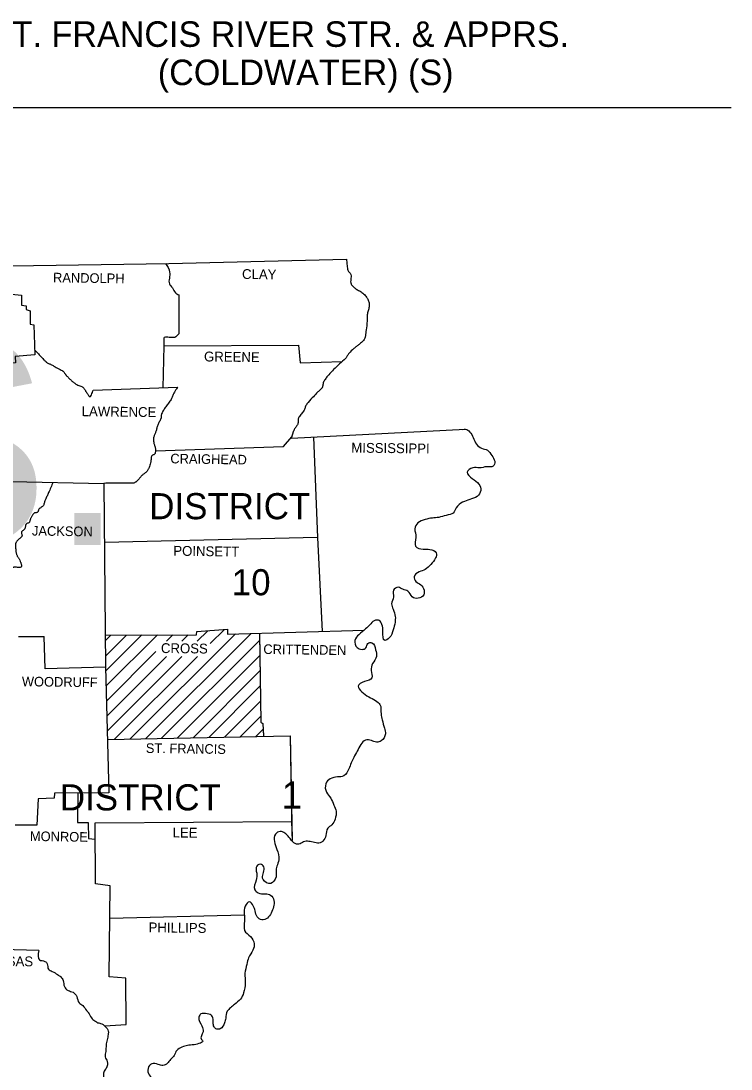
# Model space of a CAD drawing. Extents: x 1720274 to 1751788, y 372074 to 391887.
# Drawn here: x 1748526 to 1751788, y 386795 to 391611 of the extents above; entities that cross this region are included whole.
import ezdxf

# ---------------------------------------------------------------- set-up
doc = ezdxf.new("R2010")
doc.units = 0
for name, color, linetype in [('1', 7, 'Continuous'), ('Default', 7, 'Continuous'), ('G-Table-Major', 7, 'Continuous'), ('R_Draft', 7, 'Continuous')]:
    doc.layers.add(name, color=color, linetype=linetype)

msp = doc.modelspace()

# ---------------------------------------------------------------- linework, layer by layer
at = {"layer": '1'}
for p, q in [((1749768.5, 389693.6), (1749779.8, 389728.6)), ((1748513.7, 388782), (1748631.4, 388782))]:
    msp.add_line(p, q, dxfattribs=at)
for points in [[(1744246.4, 390467.3), (1745948.5, 390466.3), (1747442.1, 390469.4), (1749204.3, 390496.8), (1750021.1, 390515.7)], [(1748410.3, 390484.5), (1748406.4, 390452.6), (1748427.4, 390449.4), (1748426.4, 390436.8), (1748450.6, 390431.5), (1748452.7, 390414.7), (1748464.3, 390407.3), (1748467.4, 390356.8), (1748527.4, 390350.5), (1748527.4, 390305.2), (1748549.5, 390302), (1748549.5, 390284.2), (1748568.5, 390278.9), (1748567.4, 390217.8), (1748584.2, 390214.7), (1748588.5, 390076.8), (1748499, 390068.4), (1748500, 390038.9), (1748472.7, 390037.8), (1748482.1, 389494.7), (1748906.4, 389485.2), (1748913.7, 388641), (1748636.9, 388633.6), (1748631.4, 388782)], [(1749768.5, 389693.6), (1750567.4, 389734.7)], [(1748912.4, 388788.3), (1749332.7, 388790.4), (1749333.7, 388805.2), (1749474.8, 388815.7), (1749474.8, 388793.6), (1750101.8, 388810.8)], [(1748607.4, 387338.8), (1748209.5, 387349.3), (1748207.4, 387219.9), (1747402.2, 387216.7)]]:
    msp.add_lwpolyline(points, dxfattribs=at)
for points in [[(1750021.1, 390515.7), (1750022, 390504.1), (1750023.2, 390492.5), (1750024.7, 390481), (1750026.4, 390469.4), (1750028.8, 390462.9), (1750033.1, 390457), (1750037.7, 390451.3), (1750041.1, 390445.2), (1750042.4, 390434.5), (1750041.1, 390423), (1750040.3, 390411.5), (1750041.1, 390406.1), (1750043.2, 390401), (1750051.2, 390390.6), (1750061.1, 390382), (1750068.6, 390377), (1750076.4, 390372.6), (1750084.2, 390368.2), (1750091.6, 390363.1), (1750106.8, 390349.6), (1750113.3, 390341.8), (1750116.3, 390337.4), (1750119, 390332.6), (1750122.8, 390323.7), (1750125, 390314.7), (1750125.8, 390305.7), (1750125.3, 390296.8), (1750123.5, 390287.6), (1750120.9, 390278.4), (1750118.4, 390269.2), (1750116.9, 390259.9), (1750116.3, 390249.7), (1750115.9, 390239.4), (1750115.5, 390229.1), (1750114.8, 390218.9), (1750110.6, 390183.1), (1750108.6, 390166.6), (1750107, 390158.5), (1750105.8, 390154.5), (1750104.2, 390150.5), (1750093.3, 390135.9), (1750079, 390124.1), (1750072.9, 390119.4), (1750066.8, 390114.7), (1750060.7, 390110.1), (1750054.8, 390105.2), (1750032.7, 390083.1), (1750028.5, 390077.4), (1750025, 390071.3), (1750021.3, 390065.3), (1750016.9, 390059.9), (1749989.5, 390034.7), (1749962.1, 390008.4), (1749940, 389985.2), (1749934, 389978.2), (1749928.4, 389970.9), (1749923, 389963.4), (1749917.9, 389955.7), (1749914.7, 389947.8), (1749913.1, 389939.1), (1749911.3, 389930.5), (1749909.8, 389926.6), (1749907.4, 389923.1), (1749901.6, 389917.1), (1749895.3, 389911.4), (1749889.1, 389905.9), (1749883.2, 389899.9), (1749864.2, 389878.9), (1749839, 389850.5), (1749834.8, 389844), (1749832, 389836.7), (1749829.5, 389829.1), (1749826.4, 389822), (1749820.7, 389813.7), (1749814.1, 389805.8), (1749807.6, 389797.9), (1749802.1, 389789.4), (1749799.9, 389781.8), (1749799.3, 389773.7), (1749798.8, 389765.5), (1749796.9, 389757.8), (1749793.5, 389751.3), (1749789.3, 389745.1), (1749785, 389738.9), (1749781.1, 389732.6), (1749779.8, 389728.6)], [(1750555.8, 389733.6), (1750567.4, 389734.7), (1750603.2, 389696.8), (1750619, 389665.2), (1750642.1, 389647.3), (1750668.5, 389637.8), (1750688.5, 389613.6), (1750702.1, 389587.3), (1750694.8, 389564.1), (1750665.3, 389562), (1750632.7, 389556.8), (1750601.1, 389557.8), (1750575.8, 389536.8), (1750599, 389508.3), (1750629.5, 389482), (1750637.9, 389453.6), (1750621.1, 389426.2), (1750587.4, 389411.5), (1750554.8, 389398.9), (1750525.3, 389373.6), (1750511.6, 389349.4), (1750479, 389338.9), (1750445.3, 389329.4), (1750415.8, 389326.2), (1750382.1, 389319.9), (1750349.5, 389304.1), (1750335.8, 389276.8), (1750340, 389237.8), (1750339, 389196.8), (1750373.7, 389183.1), (1750404.2, 389182), (1750433.7, 389166.2), (1750430.6, 389143.1), (1750408.5, 389113.6), (1750382.1, 389090.4), (1750355.8, 389078.9), (1750331.6, 389056.8), (1750340, 389034.6), (1750362.1, 389019.9), (1750377.9, 388995.7), (1750375.8, 388973.6), (1750350.6, 388957.8), (1750323.2, 388964.1), (1750303.2, 388990.4), (1750280, 388998.9), (1750260, 389008.3), (1750236.9, 388994.6), (1750236.9, 388964.1), (1750228.5, 388931.5), (1750235.8, 388907.3), (1750245.3, 388873.6), (1750244.2, 388848.3), (1750235.8, 388812.5), (1750217.9, 388775.7), (1750196.9, 388764.1), (1750188.5, 388804.1), (1750184.3, 388836.7), (1750171.6, 388855.7), (1750154.8, 388856.7), (1750132.7, 388841), (1750108.5, 388816.7), (1750077.9, 388790.4), (1750060, 388764.1), (1750069.5, 388731.5), (1750092.7, 388723.1), (1750110.6, 388729.4), (1750120, 388750.4), (1750137.9, 388753.6), (1750154.8, 388721)], [(1750154.8, 388721), (1750159, 388690.4), (1750141.1, 388657.8), (1750134.8, 388625.2), (1750137.9, 388592.5), (1750104.2, 388574.6), (1750074.8, 388553.6), (1750091.6, 388528.3), (1750123.2, 388505.2), (1750154.8, 388487.3), (1750174.8, 388469.4), (1750180, 388426.2), (1750185.3, 388398.8), (1750195.8, 388360.9), (1750200, 388334.6), (1750181.1, 388303.1), (1750159, 388296.7), (1750135.8, 388304.1), (1750108.5, 388306.2), (1750086.4, 388285.2), (1750070.6, 388255.7), (1750054.8, 388226.2), (1750043.2, 388200.9), (1750031.6, 388173.6), (1750008.5, 388142), (1749980, 388136.7), (1749946.4, 388128.3), (1749926.4, 388105.2), (1749929.5, 388066.2), (1749948.5, 388039.9), (1749963.2, 388007.3), (1749973.7, 387978.8), (1749968.5, 387943), (1749953.7, 387916.7), (1749934.8, 387900.9), (1749926.4, 387867.3), (1749912.7, 387842), (1749900, 387833.6), (1749874.8, 387835.7), (1749847.4, 387840.9), (1749824.2, 387838.8), (1749802.1, 387827.2), (1749780, 387834.6), (1749756.9, 387859.9), (1749737.9, 387878.8), (1749716.9, 387886.2), (1749694.8, 387874.6), (1749690.6, 387839.9), (1749701.1, 387804.1), (1749710.6, 387755.7), (1749701.1, 387726.2), (1749697.9, 387677.8)], [(1749697.9, 387677.8), (1749673.7, 387647.2), (1749637.9, 387666.2), (1749637.9, 387691.5), (1749643.2, 387717.8), (1749630.6, 387734.6), (1749608.5, 387727.2), (1749608.5, 387694.6), (1749606.4, 387663), (1749600, 387617.8), (1749614.8, 387604.1), (1749648.5, 387599.9), (1749672.7, 387593.6), (1749687.4, 387569.3), (1749686.4, 387539.9), (1749674.8, 387511.5), (1749657.9, 387488.3), (1749631.6, 387479.9), (1749610.6, 387493.6), (1749602.1, 387520.9), (1749592.7, 387545.1), (1749574.8, 387563), (1749555.8, 387543), (1749551.6, 387506.2), (1749552.7, 387474.6), (1749552.7, 387431.5), (1749580, 387403), (1749596.9, 387370.4), (1749591.6, 387340.9), (1749571.6, 387306.2), (1749563.2, 387275.7), (1749554.8, 387234.6), (1749555.8, 387189.3), (1749548.5, 387145.1), (1749533.7, 387115.7), (1749506.4, 387091.4), (1749488.5, 387075.7), (1749473.7, 387059.9), (1749466.4, 387028.3), (1749461.1, 387006.2), (1749441.1, 386979.9), (1749425.3, 386977.8), (1749412.7, 386988.3), (1749408.5, 387006.2), (1749408.5, 387024.1), (1749400, 387042), (1749373.7, 387049.3), (1749352.7, 387048.3), (1749343.2, 387033.5), (1749356.9, 386992.5), (1749362.1, 386966.2), (1749354.8, 386930.4), (1749359, 386926.2), (1749321.1, 386906.2), (1749290.6, 386903), (1749265.3, 386895.6), (1749241.1, 386879.9), (1749229.5, 386856.7), (1749212.7, 386837.8), (1749197.9, 386819.9), (1749177.9, 386811.4), (1749155.8, 386815.6), (1749126.4, 386818.8), (1749109.5, 386797.8), (1749114.8, 386767.2), (1749134.8, 386749.3), (1749164.2, 386740.9), (1749194.8, 386743), (1749224.3, 386746.2), (1749251.6, 386731.4), (1749246.4, 386703), (1749220, 386689.3), (1749181.1, 386685.1), (1749149.5, 386688.3), (1749111.6, 386679.9), (1749092.7, 386655.6), (1749103.2, 386618.8), (1749144.3, 386604.1), (1749163.2, 386569.3), (1749164.2, 386536.7), (1749150.6, 386493.5), (1749131.6, 386473.5), (1749094.8, 386465.1), (1749066.4, 386459.8), (1749062.1, 386411.4), (1749049.5, 386387.2), (1749027.4, 386379.8), (1748995.8, 386395.6), (1748976.9, 386403), (1748953.7, 386413.5), (1748924.3, 386431.4), (1748902.1, 386428.3), (1748908.5, 386382), (1748910.6, 386379.8), (1748935.8, 386345.1), (1748961.1, 386317.7), (1748972.7, 386285.1)], [(1748607.4, 387338.8), (1748610.6, 387295.7), (1748635.8, 387289.3), (1748646.4, 387277.8), (1748651.6, 387253.6), (1748669.5, 387243), (1748693.7, 387228.3), (1748708.5, 387217.8), (1748719, 387200.9), (1748725.3, 387173.5), (1748742.1, 387155.7), (1748765.3, 387147.2), (1748782.1, 387127.2), (1748792.7, 387098.8), (1748809.5, 387086.2), (1748826.4, 387064.1), (1748834.8, 387054.6), (1748849.5, 387029.3), (1748864.3, 387016.7), (1748874.8, 387009.3), (1748891.6, 387004.1), (1748912.7, 386990.4), (1748926.4, 386969.3), (1748926.4, 386953.5), (1748921.1, 386929.3), (1748916.9, 386904.1), (1748914.8, 386875.6), (1748912.7, 386850.4), (1748922.1, 386829.3), (1748916.9, 386797.8), (1748906.4, 386780.9), (1748905.3, 386757.7), (1748902.1, 386723), (1748897.9, 386703), (1748888.5, 386670.4), (1748874.8, 386653.5)]]:
    msp.add_spline(points, degree=3, dxfattribs=at)
at = {"layer": 'Default'}
msp.add_line((1749183.3, 390117.8), (1749184.2, 390156.8), dxfattribs=at)
for points in [[(1749250.6, 390351.5), (1749250.6, 390173.6)], [(1749178.7, 389924.9), (1749183.3, 390117.8), (1749184.2, 390117.8), (1749800, 390121), (1749808.5, 390038.9), (1750001.7, 390045.9)], [(1748856.9, 389913.6), (1749245, 389927.2)], [(1749143.8, 389635.6), (1749731.6, 389654.7), (1749770.3, 389699.2)], [(1749869.3, 389698.8), (1749887.4, 389236.8), (1749908.8, 388805.5)], [(1749044.3, 389487.3), (1748915.8, 389487.3), (1748906.4, 389485.2)], [(1749887.4, 389236.8), (1748908.7, 389214.4)], [(1749622.1, 388797.6), (1749627.4, 388388.3), (1749636.9, 388382), (1749640.2, 388323.8)], [(1749622.1, 388793.6), (1749627.4, 388388.3), (1749636.9, 388382), (1749640, 388327.3)], [(1749622.1, 388793.6), (1749627.4, 388388.3), (1749636.9, 388382), (1749640, 388327.3)], [(1749622.1, 388793.6), (1749627.4, 388388.3), (1749636.9, 388382), (1749640, 388327.3)], [(1749622.1, 388793.6), (1749627.4, 388388.3), (1749636.9, 388382), (1749640, 388327.3)], [(1748913.7, 388641), (1748929.5, 388064.1), (1748679, 388063), (1748677.9, 388039.9), (1748605.3, 388035.7), (1748599, 387915.7), (1748499.2, 387915.7)], [(1748922.8, 388309.3), (1749762.1, 388326.2)], [(1749762.1, 388326.2), (1749770.6, 387865.1)], [(1749762.1, 388326.2), (1749770.6, 387865.1)], [(1749762.1, 388326.2), (1749770.6, 387865.1)], [(1749762.1, 388326.2), (1749770.6, 387865.1)], [(1749762.1, 388326.2), (1749770.6, 387865.1)], [(1749762.1, 388326.2), (1749770.6, 387865.1)], [(1749762.1, 388326.2), (1749770.6, 387865.1)], [(1749762.1, 388326.2), (1749771, 387844)], [(1748786.4, 388063.5), (1748785.3, 387927.3), (1748833.7, 387927.3), (1748835.8, 387854.6), (1748866.9, 387851.4)], [(1748910.3, 386992.5), (1749008.5, 386998.8), (1749007.4, 387212.5), (1748930.6, 387217.8), (1748934.8, 387635.7), (1748868.5, 387645.1), (1748866.4, 387926.2), (1749769.3, 387932.6)], [(1748933.3, 387487.2), (1749551.8, 387502.5)]]:
    msp.add_lwpolyline(points, dxfattribs=at)
for points in [[(1749189.4, 390496.6), (1749208.5, 390456.8), (1749207.4, 390428.4), (1749207.4, 390402.1), (1749221.1, 390384.2), (1749234.8, 390362), (1749250.6, 390351.5)], [(1749250.6, 390173.6), (1749232.7, 390156.8), (1749206.4, 390156.8), (1749184.2, 390156.8)], [(1748587.8, 390098.9), (1748605.4, 390080.4), (1748623.2, 390062), (1748625.7, 390059.5), (1748633, 390051.8), (1748637.9, 390046.8), (1748640.5, 390044.4), (1748641.8, 390043.2), (1748643.2, 390042), (1748648.6, 390038.5), (1748654.5, 390035.8), (1748660.5, 390033.3), (1748666.4, 390030.5), (1748680, 390022.6), (1748693.7, 390014.7), (1748699.8, 390011.5), (1748705.9, 390008.6), (1748715, 390003.9), (1748716.5, 390003), (1748717.9, 390002), (1748722.6, 389997.7), (1748726.3, 389992.5), (1748729.8, 389987.1), (1748731.7, 389984.5), (1748733.7, 389982), (1748744.6, 389970.8), (1748755.8, 389959.9), (1748761.2, 389955.2), (1748766.7, 389950.7), (1748772.3, 389946.3), (1748777.9, 389942), (1748786.6, 389937.6), (1748796.1, 389934.6), (1748805.3, 389931), (1748809.3, 389928.5), (1748811.1, 389927), (1748812.7, 389925.2), (1748815.8, 389920.9), (1748818.6, 389916.4), (1748821.3, 389911.8), (1748824.3, 389907.3), (1748826.2, 389904.4), (1748828.2, 389901.3), (1748832.1, 389895.2), (1748836.1, 389889.6), (1748838.1, 389887.2), (1748839.1, 389886.1), (1748839.6, 389885.6), (1748840, 389885.2), (1748841.2, 389884.5), (1748842.4, 389884.3), (1748844.8, 389885.7), (1748849.3, 389893.2), (1748853.5, 389903.8), (1748855.3, 389909.1), (1748856.9, 389913.6)], [(1749245, 389927.2), (1749236.1, 389914.4), (1749228.5, 389901), (1749225.2, 389893.7), (1749222.4, 389886.1), (1749219.4, 389878.6), (1749215.8, 389871.5), (1749209.9, 389862.8), (1749203.4, 389854.5), (1749196.8, 389846.3), (1749190.6, 389837.8), (1749180.4, 389821.9), (1749175.8, 389813.7), (1749171.6, 389805.2), (1749170.2, 389799.8), (1749169.9, 389794.2), (1749169.6, 389788.5), (1749168.5, 389783.1), (1749165, 389775.6), (1749160.9, 389768.4), (1749156.9, 389761.2), (1749153.7, 389753.6), (1749151.5, 389746.3), (1749149.5, 389738.9), (1749147.5, 389731.5), (1749145.3, 389724.1), (1749143, 389717.8), (1749140.5, 389711.6), (1749138, 389705.3), (1749135.8, 389698.9), (1749134.7, 389692.4), (1749134.5, 389685.8), (1749135, 389679.1), (1749135.8, 389672.6), (1749137.3, 389665.9), (1749139.4, 389659.4), (1749141.6, 389652.8), (1749143.2, 389646.2), (1749143.8, 389640.3), (1749143.7, 389634.1), (1749142.8, 389628), (1749142, 389625), (1749141.1, 389622), (1749137.9, 389618.4), (1749133, 389616.2), (1749128.2, 389614), (1749125.3, 389610.5), (1749124.5, 389606.7), (1749123.9, 389602.9), (1749123.2, 389595.2), (1749122.4, 389587.5), (1749121.1, 389579.9), (1749118.3, 389569.3), (1749114.8, 389558.9), (1749108.9, 389547.7), (1749105.3, 389542.6), (1749101.1, 389537.8), (1749096.3, 389533.5), (1749091.1, 389529.8), (1749085.9, 389526.1), (1749081.1, 389522), (1749075.7, 389516.2), (1749070.7, 389510), (1749065.6, 389503.7), (1749060, 389497.8), (1749052.7, 389492), (1749048.6, 389489.5), (1749044.3, 389487.3)], [(1748672.3, 389490.4), (1748662.9, 389466.6), (1748652.7, 389443.1), (1748649, 389435.1), (1748645.3, 389427.3), (1748641.6, 389419.4), (1748637.9, 389411.5), (1748635.3, 389404.8), (1748633.2, 389397.8), (1748631.1, 389390.9), (1748628.5, 389384.1), (1748624.6, 389379.3), (1748619.1, 389375.7), (1748613.3, 389372.3), (1748610.7, 389370.5), (1748608.5, 389368.3), (1748606.6, 389364.9), (1748605.4, 389360.9), (1748604.2, 389356.9), (1748602.1, 389353.6), (1748598.2, 389351.4), (1748593.2, 389350.6), (1748588.2, 389349.7), (1748584.2, 389347.3), (1748582.2, 389344.9), (1748580.3, 389342.4), (1748576.7, 389337.2), (1748573.5, 389331.8), (1748570.6, 389326.2), (1748568.8, 389321.6), (1748567.5, 389316.7), (1748566.2, 389311.8), (1748564.3, 389307.3), (1748561.3, 389304.5), (1748557, 389302.9), (1748552.8, 389301.4), (1748549.5, 389298.9), (1748548.1, 389296.3), (1748547, 389293.5), (1748545.6, 389287.3), (1748544.3, 389281.1), (1748542.8, 389277), (1748542.1, 389275.7), (1748539.1, 389272.4), (1748535.2, 389269.5), (1748531.4, 389266.5), (1748528.5, 389263.1), (1748527.9, 389258.1), (1748529.4, 389252.4), (1748530.7, 389246.8), (1748529.5, 389242), (1748528.7, 389241), (1748527.7, 389240), (1748521.7, 389234.6), (1748517.6, 389231.1), (1748513.7, 389227.3), (1748510.1, 389223.4), (1748506.6, 389219.5), (1748503.4, 389215.2), (1748502.1, 389212.9), (1748501.1, 389210.4), (1748499.8, 389198.9), (1748501.1, 389187.3), (1748501.9, 389179.6), (1748502.7, 389171.9), (1748504.1, 389164.3), (1748505.1, 389160.5), (1748506.4, 389156.8), (1748508.6, 389152), (1748511.4, 389147.7), (1748514.3, 389143.4), (1748516.9, 389138.9), (1748522, 389127.4), (1748524.3, 389121.5), (1748526.4, 389115.7), (1748527.5, 389112), (1748528.2, 389107.9), (1748527.7, 389104.1), (1748526.8, 389102.4), (1748526.1, 389101.7), (1748525.3, 389101), (1748518.8, 389098.5), (1748512.2, 389099.1), (1748505.5, 389100.7), (1748502.2, 389101.1), (1748499, 389101), (1748493.5, 389100), (1748487.9, 389099.1), (1748482.4, 389098), (1748476.9, 389096.8)]]:
    msp.add_spline(points, degree=3, dxfattribs=at)
at = {"layer": 'G-Table-Major'}
msp.add_line((1747806, 391213.6), (1751788, 391213.6), dxfattribs=at)
at = {"layer": 'R_Draft'}
for p, q in [((1749027.6, 388311.4), (1749510.7, 388794.6)), ((1749099.7, 388312.9), (1749583.4, 388796.6)), ((1749335.5, 388760.8), (1749383.6, 388808.9)), ((1749395.1, 388749.6), (1749460, 388814.6)), ((1748912.7, 388762.2), (1748938.9, 388788.4)), ((1748913.3, 388692.1), (1749009.9, 388788.8)), ((1748914.2, 388622.3), (1749081, 388789.1)), ((1748916.1, 388553.5), (1749152.1, 388789.5)), ((1749171.9, 388314.3), (1749622.5, 388764.9)), ((1749194.1, 388760.8), (1749223.2, 388789.9)), ((1749264.8, 388760.8), (1749294.3, 388790.2)), ((1748918, 388484.7), (1749145.8, 388712.5)), ((1748919.9, 388415.9), (1749194.7, 388690.7)), ((1748921.8, 388347), (1749265.4, 388690.7)), ((1748955.4, 388310), (1749336.1, 388690.7)), ((1749244.1, 388315.8), (1749623.4, 388695.1)), ((1749316.2, 388317.2), (1749624.3, 388625.3)), ((1749388.4, 388318.7), (1749625.2, 388555.5)), ((1749460.5, 388320.1), (1749626.1, 388485.7)), ((1749532.7, 388321.6), (1749627, 388415.9)), ((1749604.9, 388323), (1749638.4, 388356.5))]:
    msp.add_line(p, q, dxfattribs=at)

# ---------------------------------------------------------------- texts
at = {"layer": '1'}
for s, p in [('ST. FRANCIS RIVER STR. & APPRS.', (1748378.3, 391491.6)), ('(COLDWATER) (S)', (1749154.3, 391315.7))]:
    msp.add_text(s, height=117.24, dxfattribs=at).set_placement(p)
at = {"layer": 'Default'}
for s, height, rotation, p in [('RANDOLPH', 44.22, 359.2583, (1748672.7, 390409.4)), ('CLAY', 45.26, 359.2258, (1749541.1, 390425.2)), ('GREENE', 45.27, 359.2361, (1749366.4, 390046.3)), ('LAWRENCE', 45.27, 359.2678, (1748804.2, 389794.7)), ('MISSISSIPPI', 45.259, 359.3097, (1750043.2, 389627.3)), ('CRAIGHEAD', 44.22, 359.1159, (1749211.6, 389577.8)), ('JACKSON', 44.2, 359.1352, (1748575.8, 389246.2)), ('POINSETT', 45.26, 359.1987, (1749225.3, 389153.6)), ('CROSS', 45.26, 359.3839, (1749168.5, 388706.2)), ('CRITTENDEN', 44.22, 359.213, (1749639, 388702)), ('WOODRUFF', 44.2, 359.2748, (1748529.5, 388553.6)), ('ST. FRANCIS', 44.205, 359.2216, (1749099, 388247.3)), ('MONROE', 44.2, 359.0331, (1748566.4, 387843)), ('LEE', 45.27, 359.4327, (1749222.1, 387858.8)), ('PHILLIPS', 45.26, 359.3179, (1749111.6, 387423)), ('ARKANSAS', 45.26, 359.2678, (1748251.6, 387270.4))]:
    msp.add_text(s, height=height, rotation=rotation, dxfattribs=at).set_placement(p)
for s, height, p in [('DISTRICT', 120, (1749114.8, 389321)), ('10', 120, (1749494, 388971.5)), ('DISTRICT', 120, (1748704.3, 387983)), ('1', 126.3, (1749723.2, 387990.4))]:
    msp.add_text(s, height=height, dxfattribs=at).set_placement(p)
at = {"layer": 'R_Draft'}
msp.add_text('ST. FRANCIS RIVER STR. & APPRS.', height=947.368, dxfattribs=at).set_placement((1727467, 389202))

doc.saveas('drawing.dxf')
